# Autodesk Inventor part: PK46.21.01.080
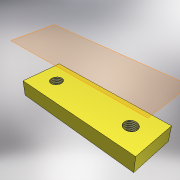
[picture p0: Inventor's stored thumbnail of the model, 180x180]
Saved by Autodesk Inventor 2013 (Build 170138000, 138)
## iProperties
Created: 2005-05
Part Number: PK46.21.01.080
Material: Steel, Mild
Document SubType Name: Modeling
Designer: elarisa
Manufacturer: Standard
Standards Organization: Custom
Density: 7.86 g/cm^3
Mass: 539.252 g
Surface Area: 150.786 cm^2
Volume: 68.6071 cm^3
Author: elarisa
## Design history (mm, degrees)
sketch "Эскиз1"
  geometry: L1 (-13.2, 20.6)-(106.8, 20.6); L2 (106.8, 20.6)-(106.8, -19.4); L3 (106.8, -19.4)-(-13.2, -19.4); L4 (-13.2, -19.4)-(-13.2, 20.6); C1 r 6 at (6.8, 0.6); C2 r 6 at (86.8, 0.6)
  constraints: 8 end point, 2 centre point, 2 parallel, 1 horizontal, 1 perpendicular
  dimensions: "d0" = 40 distance of L3.end L1.start; "d1" = 120 distance of L1.start L1.end; "d2" = 12 diameter of C1; "d3" = 12 diameter of C2; "d4" = 20 distance from line of L3 C1.centre; "d5" = 20 distance from line of L4 C1.centre; "d6" = 20 distance from line of L2 C2.centre; "d7" = 0 vertical distance of C2.centre C1.centre
extrude "Выдавливание1" new body sketch "Эскиз1" distance "d8" = 15; taper "d9" = 0 deg
feature "Резьба1" dims "d10" = 10, "d11" = 0
feature "Резьба2" dims "d12" = 10, "d13" = 0
node "РабПлоскость1"
body "Solid1"
other parameters: "d14" = 36
